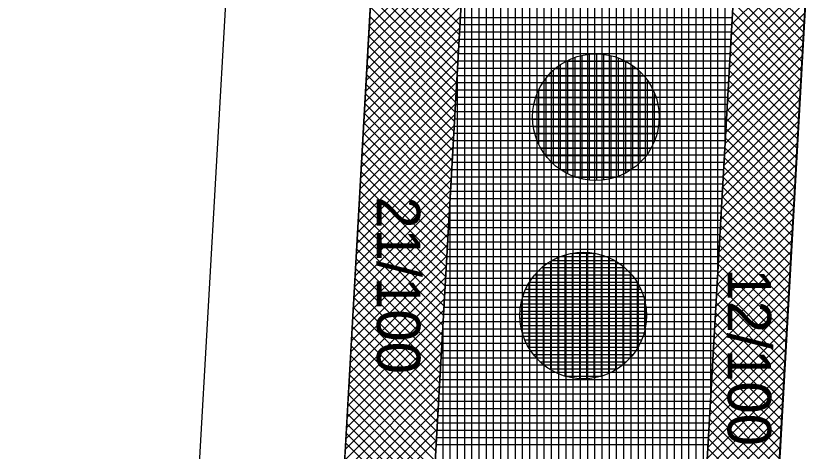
# Model space of a CAD drawing. Extents: x -565346 to -564154, y -1097386 to -1095620.
# Drawn here: x -564304.4 to -564282.47, y -1097114.37 to -1097102.35 of the extents above; entities that cross this region are included whole.
import ezdxf

# ---------------------------------------------------------------- set-up
doc = ezdxf.new("R2010")
doc.units = 0
for name, color, linetype in [('Vrstva 1', 7, 'Continuous'), ('Vrstva 13', 7, 'Continuous'), ('Vrstva 40', 7, 'Continuous'), ('Vrstva 41', 7, 'Continuous'), ('Vrstva 42', 7, 'Continuous'), ('Vrstva 43', 7, 'Continuous'), ('Vrstva 44', 7, 'Continuous')]:
    doc.layers.add(name, color=color, linetype=linetype)

msp = doc.modelspace()

# ---------------------------------------------------------------- linework, layer by layer
at = {"layer": 'Vrstva 1'}
for p, q in [((-564296.5, -1097135.53), (-564285.9, -1096948.97)), ((-564296.48, -1097064.53), (-564302.81, -1097176.11))]:
    msp.add_line(p, q, dxfattribs=at)
at = {"layer": 'Vrstva 13'}
msp.add_line((-564277.71, -1097016.43), (-564284.61, -1097137.94), dxfattribs=at)
at = {"layer": 'Vrstva 41'}
for points in [[(-564296.782, -1097140.492), (-564294.286, -1097140.634), (-564282.373, -1096930.972), (-564284.87, -1096930.83)], [(-564272.899, -1096931.51), (-564274.888, -1096931.397), (-564286.791, -1097141.059), (-564284.798, -1097141.172)]]:
    msp.add_lwpolyline(points, close=True, dxfattribs=at)
at = {"layer": 'Vrstva 42'}
for p, q in [((-564291.976, -1097099.978), (-564294.631, -1097102.633)), ((-564291.993, -1097100.278), (-564294.648, -1097102.933)), ((-564294.494, -1097100.221), (-564292.124, -1097102.591)), ((-564294.509, -1097100.489), (-564292.14, -1097102.858)), ((-564282.487, -1097100.46), (-564284.606, -1097102.579)), ((-564292.01, -1097100.578), (-564294.665, -1097103.233)), ((-564284.496, -1097100.643), (-564282.605, -1097102.534)), ((-564292.027, -1097100.878), (-564294.682, -1097103.533)), ((-564294.524, -1097100.757), (-564292.155, -1097103.126)), ((-564282.504, -1097100.76), (-564284.623, -1097102.879)), ((-564284.512, -1097100.91), (-564282.62, -1097102.802)), ((-564294.539, -1097101.024), (-564292.17, -1097103.394)), ((-564282.521, -1097101.059), (-564284.64, -1097103.179)), ((-564292.044, -1097101.178), (-564294.699, -1097103.833)), ((-564294.555, -1097101.292), (-564292.185, -1097103.661)), ((-564282.538, -1097101.359), (-564284.657, -1097103.478)), ((-564284.527, -1097101.178), (-564282.635, -1097103.069)), ((-564292.061, -1097101.478), (-564294.716, -1097104.132)), ((-564294.57, -1097101.559), (-564292.2, -1097103.929)), ((-564284.542, -1097101.446), (-564282.651, -1097103.337)), ((-564292.078, -1097101.777), (-564294.733, -1097104.432)), ((-564294.585, -1097101.827), (-564292.216, -1097104.196)), ((-564282.555, -1097101.659), (-564284.674, -1097103.778)), ((-564284.557, -1097101.713), (-564282.666, -1097103.605)), ((-564282.572, -1097101.959), (-564284.692, -1097104.078)), ((-564284.572, -1097101.981), (-564282.681, -1097103.872)), ((-564292.095, -1097102.077), (-564294.75, -1097104.732)), ((-564294.6, -1097102.095), (-564292.231, -1097104.464)), ((-564282.589, -1097102.259), (-564284.709, -1097104.378)), ((-564284.588, -1097102.249), (-564282.696, -1097104.14)), ((-564292.112, -1097102.377), (-564294.767, -1097105.032)), ((-564294.615, -1097102.362), (-564292.246, -1097104.732)), ((-564292.129, -1097102.677), (-564294.784, -1097105.332)), ((-564294.631, -1097102.63), (-564292.261, -1097104.999)), ((-564282.606, -1097102.559), (-564284.726, -1097104.678)), ((-564284.603, -1097102.516), (-564282.711, -1097104.408)), ((-564294.646, -1097102.898), (-564292.276, -1097105.267)), ((-564282.623, -1097102.859), (-564284.743, -1097104.978)), ((-564284.618, -1097102.784), (-564282.727, -1097104.675)), ((-564292.146, -1097102.977), (-564294.801, -1097105.632)), ((-564284.633, -1097103.052), (-564282.742, -1097104.943)), ((-564292.163, -1097103.277), (-564294.818, -1097105.932)), ((-564294.661, -1097103.165), (-564292.292, -1097105.535)), ((-564282.64, -1097103.158), (-564284.76, -1097105.278)), ((-564284.648, -1097103.319), (-564282.757, -1097105.211)), ((-564292.18, -1097103.577), (-564294.835, -1097106.232)), ((-564294.676, -1097103.433), (-564292.307, -1097105.802)), ((-564282.657, -1097103.458), (-564284.777, -1097105.577)), ((-564284.664, -1097103.587), (-564282.772, -1097105.478)), ((-564294.691, -1097103.701), (-564292.322, -1097106.07)), ((-564282.675, -1097103.758), (-564284.794, -1097105.877)), ((-564292.197, -1097103.877), (-564294.852, -1097106.531)), ((-564294.707, -1097103.968), (-564292.337, -1097106.338)), ((-564284.679, -1097103.854), (-564282.787, -1097105.746)), ((-564292.214, -1097104.177), (-564294.869, -1097106.831)), ((-564294.722, -1097104.236), (-564292.352, -1097106.605)), ((-564282.692, -1097104.058), (-564284.811, -1097106.177)), ((-564284.694, -1097104.122), (-564282.803, -1097106.014)), ((-564282.709, -1097104.358), (-564284.828, -1097106.477)), ((-564284.709, -1097104.39), (-564282.818, -1097106.281)), ((-564292.232, -1097104.476), (-564294.886, -1097107.131)), ((-564294.737, -1097104.503), (-564292.368, -1097106.873)), ((-564282.726, -1097104.658), (-564284.845, -1097106.777)), ((-564284.724, -1097104.657), (-564282.833, -1097106.549)), ((-564292.249, -1097104.776), (-564294.903, -1097107.431)), ((-564294.752, -1097104.771), (-564292.383, -1097107.14)), ((-564292.266, -1097105.076), (-564294.92, -1097107.731)), ((-564294.767, -1097105.039), (-564292.398, -1097107.408)), ((-564282.743, -1097104.958), (-564284.862, -1097107.077)), ((-564284.74, -1097104.925), (-564282.848, -1097106.817)), ((-564294.783, -1097105.306), (-564292.413, -1097107.676)), ((-564282.76, -1097105.257), (-564284.879, -1097107.377)), ((-564284.755, -1097105.193), (-564282.863, -1097107.084)), ((-564292.283, -1097105.376), (-564294.937, -1097108.031)), ((-564282.777, -1097105.557), (-564284.896, -1097107.677)), ((-564284.77, -1097105.46), (-564282.878, -1097107.352)), ((-564292.3, -1097105.676), (-564294.955, -1097108.331)), ((-564294.798, -1097105.574), (-564292.429, -1097107.943)), ((-564284.785, -1097105.728), (-564282.894, -1097107.62)), ((-564292.317, -1097105.976), (-564294.972, -1097108.631)), ((-564294.813, -1097105.842), (-564292.444, -1097108.211)), ((-564282.794, -1097105.857), (-564284.913, -1097107.976)), ((-564284.8, -1097105.996), (-564282.909, -1097107.887)), ((-564294.828, -1097106.109), (-564292.459, -1097108.479)), ((-564282.811, -1097106.157), (-564284.93, -1097108.276)), ((-564292.334, -1097106.276), (-564294.989, -1097108.931)), ((-564294.844, -1097106.377), (-564292.474, -1097108.746)), ((-564284.816, -1097106.263), (-564282.924, -1097108.155)), ((-564292.351, -1097106.576), (-564295.006, -1097109.23)), ((-564294.859, -1097106.645), (-564292.489, -1097109.014)), ((-564282.828, -1097106.457), (-564284.947, -1097108.576)), ((-564284.831, -1097106.531), (-564282.939, -1097108.422)), ((-564292.368, -1097106.875), (-564295.023, -1097109.53)), ((-564282.845, -1097106.757), (-564284.964, -1097108.876)), ((-564284.846, -1097106.799), (-564282.954, -1097108.69)), ((-564294.874, -1097106.912), (-564292.505, -1097109.282)), ((-564282.862, -1097107.057), (-564284.981, -1097109.176)), ((-564284.861, -1097107.066), (-564282.97, -1097108.958)), ((-564292.385, -1097107.175), (-564295.04, -1097109.83)), ((-564294.889, -1097107.18), (-564292.52, -1097109.549)), ((-564292.402, -1097107.475), (-564295.057, -1097110.13)), ((-564294.904, -1097107.447), (-564292.535, -1097109.817)), ((-564282.879, -1097107.356), (-564284.998, -1097109.476)), ((-564284.876, -1097107.334), (-564282.985, -1097109.225)), ((-564294.92, -1097107.715), (-564292.55, -1097110.084)), ((-564282.896, -1097107.656), (-564285.015, -1097109.776)), ((-564284.892, -1097107.602), (-564283, -1097109.493)), ((-564292.419, -1097107.775), (-564295.074, -1097110.43)), ((-564282.913, -1097107.956), (-564285.032, -1097110.075)), ((-564284.907, -1097107.869), (-564283.015, -1097109.761)), ((-564292.436, -1097108.075), (-564295.091, -1097110.73)), ((-564294.935, -1097107.983), (-564292.565, -1097110.352)), ((-564284.922, -1097108.137), (-564283.03, -1097110.028)), ((-564292.453, -1097108.375), (-564295.108, -1097111.03)), ((-564294.95, -1097108.25), (-564292.581, -1097110.62)), ((-564282.93, -1097108.256), (-564285.049, -1097110.375)), ((-564284.937, -1097108.404), (-564283.046, -1097110.296)), ((-564294.965, -1097108.518), (-564292.596, -1097110.887)), ((-564282.947, -1097108.556), (-564285.066, -1097110.675)), ((-564292.47, -1097108.675), (-564295.125, -1097111.33)), ((-564294.98, -1097108.786), (-564292.611, -1097111.155)), ((-564284.952, -1097108.672), (-564283.061, -1097110.564)), ((-564292.487, -1097108.975), (-564295.142, -1097111.629)), ((-564294.996, -1097109.053), (-564292.626, -1097111.423)), ((-564282.964, -1097108.856), (-564285.083, -1097110.975)), ((-564284.968, -1097108.94), (-564283.076, -1097110.831)), ((-564292.504, -1097109.274), (-564295.159, -1097111.929)), ((-564282.981, -1097109.156), (-564285.1, -1097111.275)), ((-564284.983, -1097109.207), (-564283.091, -1097111.099)), ((-564295.011, -1097109.321), (-564292.641, -1097111.69)), ((-564282.998, -1097109.456), (-564285.117, -1097111.575)), ((-564284.998, -1097109.475), (-564283.106, -1097111.367)), ((-564292.521, -1097109.574), (-564295.176, -1097112.229)), ((-564295.026, -1097109.589), (-564292.657, -1097111.958)), ((-564292.538, -1097109.874), (-564295.193, -1097112.529)), ((-564295.041, -1097109.856), (-564292.672, -1097112.226)), ((-564283.015, -1097109.755), (-564285.134, -1097111.875)), ((-564285.013, -1097109.743), (-564283.121, -1097111.634)), ((-564295.056, -1097110.124), (-564292.687, -1097112.493)), ((-564283.032, -1097110.055), (-564285.151, -1097112.175)), ((-564285.028, -1097110.01), (-564283.137, -1097111.902)), ((-564292.555, -1097110.174), (-564295.21, -1097112.829)), ((-564283.049, -1097110.355), (-564285.168, -1097112.474)), ((-564285.043, -1097110.278), (-564283.152, -1097112.17)), ((-564292.572, -1097110.474), (-564295.227, -1097113.129)), ((-564295.072, -1097110.391), (-564292.702, -1097112.761)), ((-564285.059, -1097110.546), (-564283.167, -1097112.437)), ((-564292.589, -1097110.774), (-564295.244, -1097113.429)), ((-564295.087, -1097110.659), (-564292.717, -1097113.028)), ((-564283.066, -1097110.655), (-564285.185, -1097112.774)), ((-564285.074, -1097110.813), (-564283.182, -1097112.705)), ((-564295.102, -1097110.927), (-564292.733, -1097113.296)), ((-564283.083, -1097110.955), (-564285.202, -1097113.074)), ((-564292.606, -1097111.074), (-564295.261, -1097113.729)), ((-564295.117, -1097111.194), (-564292.748, -1097113.564)), ((-564283.1, -1097111.255), (-564285.219, -1097113.374)), ((-564285.089, -1097111.081), (-564283.197, -1097112.973)), ((-564292.623, -1097111.374), (-564295.278, -1097114.028)), ((-564295.132, -1097111.462), (-564292.763, -1097113.831)), ((-564285.104, -1097111.349), (-564283.213, -1097113.24)), ((-564292.64, -1097111.674), (-564295.295, -1097114.328)), ((-564283.117, -1097111.555), (-564285.236, -1097113.674)), ((-564285.119, -1097111.616), (-564283.228, -1097113.508)), ((-564295.148, -1097111.73), (-564292.778, -1097114.099)), ((-564283.134, -1097111.854), (-564285.253, -1097113.974)), ((-564285.135, -1097111.884), (-564283.243, -1097113.776)), ((-564292.658, -1097111.973), (-564295.312, -1097114.628)), ((-564295.163, -1097111.997), (-564292.793, -1097114.367)), ((-564292.675, -1097112.273), (-564295.329, -1097114.928)), ((-564295.178, -1097112.265), (-564292.809, -1097114.634)), ((-564283.151, -1097112.154), (-564285.27, -1097114.274)), ((-564285.15, -1097112.152), (-564283.258, -1097114.043)), ((-564292.692, -1097112.573), (-564295.346, -1097115.228)), ((-564295.193, -1097112.533), (-564292.824, -1097114.902)), ((-564283.168, -1097112.454), (-564285.287, -1097114.573)), ((-564285.165, -1097112.419), (-564283.273, -1097114.311)), ((-564283.185, -1097112.754), (-564285.304, -1097114.873)), ((-564285.18, -1097112.687), (-564283.289, -1097114.579)), ((-564292.709, -1097112.873), (-564295.363, -1097115.528)), ((-564295.208, -1097112.8), (-564292.839, -1097115.17)), ((-564285.195, -1097112.955), (-564283.304, -1097114.846)), ((-564292.726, -1097113.173), (-564295.38, -1097115.828)), ((-564295.224, -1097113.068), (-564292.854, -1097115.437)), ((-564283.202, -1097113.054), (-564285.321, -1097115.173)), ((-564285.211, -1097113.222), (-564283.319, -1097115.114)), ((-564295.239, -1097113.335), (-564292.87, -1097115.705)), ((-564283.219, -1097113.354), (-564285.338, -1097115.473)), ((-564292.743, -1097113.473), (-564295.397, -1097116.128)), ((-564295.254, -1097113.603), (-564292.885, -1097115.972)), ((-564283.236, -1097113.654), (-564285.355, -1097115.773)), ((-564285.226, -1097113.49), (-564283.334, -1097115.381)), ((-564292.76, -1097113.773), (-564295.415, -1097116.427)), ((-564295.269, -1097113.871), (-564292.9, -1097116.24)), ((-564285.241, -1097113.757), (-564283.349, -1097115.649)), ((-564292.777, -1097114.073), (-564295.432, -1097116.727)), ((-564283.253, -1097113.953), (-564285.372, -1097116.073)), ((-564285.256, -1097114.025), (-564283.365, -1097115.917)), ((-564295.284, -1097114.138), (-564292.915, -1097116.508)), ((-564283.27, -1097114.253), (-564285.389, -1097116.373)), ((-564285.271, -1097114.293), (-564283.38, -1097116.184))]:
    msp.add_line(p, q, dxfattribs=at)
at = {"layer": 'Vrstva 43'}
for p, q in [((-564284.79, -1097105.813), (-564284.79, -1096973.51)), ((-564284.99, -1097109.336), (-564284.99, -1096977.03)), ((-564285.19, -1097112.859), (-564285.19, -1096980.55)), ((-564285.39, -1097116.382), (-564285.39, -1096984.069)), ((-564285.59, -1097119.904), (-564285.59, -1096987.589)), ((-564285.79, -1097123.427), (-564285.79, -1096991.109)), ((-564285.99, -1097126.95), (-564285.99, -1096994.629)), ((-564286.19, -1097130.473), (-564286.19, -1096998.149)), ((-564286.39, -1097133.996), (-564286.39, -1097001.669)), ((-564286.59, -1097137.519), (-564286.59, -1097005.189)), ((-564286.79, -1097141.041), (-564286.79, -1097008.709)), ((-564286.99, -1097151.064), (-564286.99, -1097012.229)), ((-564287.19, -1097151.053), (-564287.19, -1097015.748)), ((-564287.39, -1097151.606), (-564287.39, -1097019.268)), ((-564287.59, -1097155.126), (-564287.59, -1097022.788)), ((-564287.79, -1097158.646), (-564287.79, -1097026.308)), ((-564287.99, -1097162.166), (-564287.99, -1097029.828)), ((-564288.19, -1097165.686), (-564288.19, -1097033.348)), ((-564288.39, -1097169.206), (-564288.39, -1097036.868)), ((-564288.59, -1097172.726), (-564288.59, -1097040.388)), ((-564288.79, -1097176.246), (-564288.79, -1097043.908)), ((-564288.99, -1097179.766), (-564288.99, -1097047.427)), ((-564289.19, -1097183.288), (-564289.19, -1097050.947)), ((-564289.39, -1097186.812), (-564289.39, -1097054.467)), ((-564289.59, -1097190.335), (-564289.59, -1097057.987)), ((-564289.79, -1097193.858), (-564289.79, -1097061.507)), ((-564289.99, -1097197.382), (-564289.99, -1097065.027)), ((-564290.19, -1097200.905), (-564290.19, -1097068.547)), ((-564290.39, -1097204.428), (-564290.39, -1097072.067)), ((-564290.59, -1097207.951), (-564290.59, -1097075.587)), ((-564290.79, -1097211.475), (-564290.79, -1097079.106)), ((-564290.99, -1097214.998), (-564290.99, -1097082.626)), ((-564291.19, -1097218.521), (-564291.19, -1097086.146)), ((-564291.39, -1097222.044), (-564291.39, -1097089.666)), ((-564291.59, -1097225.568), (-564291.59, -1097093.186)), ((-564291.79, -1097229.091), (-564291.79, -1097096.706)), ((-564291.99, -1097232.614), (-564291.99, -1097100.226)), ((-564292.113, -1097102.39), (-564284.596, -1097102.39)), ((-564292.124, -1097102.59), (-564284.607, -1097102.59)), ((-564292.136, -1097102.79), (-564284.618, -1097102.79)), ((-564292.147, -1097102.99), (-564284.63, -1097102.99)), ((-564292.158, -1097103.19), (-564284.641, -1097103.19)), ((-564292.17, -1097103.39), (-564284.652, -1097103.39)), ((-564292.193, -1097103.79), (-564284.675, -1097103.79)), ((-564292.19, -1097236.137), (-564292.19, -1097103.746)), ((-564292.181, -1097103.59), (-564284.664, -1097103.59)), ((-564292.204, -1097103.99), (-564284.687, -1097103.99)), ((-564292.215, -1097104.19), (-564284.698, -1097104.19)), ((-564292.227, -1097104.39), (-564284.709, -1097104.39)), ((-564292.238, -1097104.59), (-564284.721, -1097104.59)), ((-564292.249, -1097104.79), (-564284.732, -1097104.79)), ((-564292.261, -1097104.99), (-564284.743, -1097104.99)), ((-564292.272, -1097105.19), (-564284.755, -1097105.19)), ((-564292.283, -1097105.39), (-564284.766, -1097105.39)), ((-564292.295, -1097105.59), (-564284.777, -1097105.59)), ((-564292.318, -1097105.99), (-564284.8, -1097105.99)), ((-564292.306, -1097105.79), (-564284.789, -1097105.79)), ((-564292.329, -1097106.19), (-564284.811, -1097106.19)), ((-564292.34, -1097106.39), (-564284.823, -1097106.39)), ((-564292.352, -1097106.59), (-564284.834, -1097106.59)), ((-564292.363, -1097106.79), (-564284.845, -1097106.79)), ((-564292.374, -1097106.99), (-564284.857, -1097106.99)), ((-564292.39, -1097239.661), (-564292.39, -1097107.266)), ((-564292.386, -1097107.19), (-564284.868, -1097107.19)), ((-564292.397, -1097107.39), (-564284.88, -1097107.39)), ((-564292.408, -1097107.59), (-564284.891, -1097107.59)), ((-564292.42, -1097107.79), (-564284.902, -1097107.79)), ((-564292.443, -1097108.19), (-564284.925, -1097108.19)), ((-564292.431, -1097107.99), (-564284.914, -1097107.99)), ((-564292.454, -1097108.39), (-564284.936, -1097108.39)), ((-564292.465, -1097108.59), (-564284.948, -1097108.59)), ((-564292.477, -1097108.79), (-564284.959, -1097108.79)), ((-564292.488, -1097108.99), (-564284.97, -1097108.99)), ((-564292.499, -1097109.19), (-564284.982, -1097109.19)), ((-564292.511, -1097109.39), (-564284.993, -1097109.39)), ((-564292.522, -1097109.59), (-564285.004, -1097109.59)), ((-564292.533, -1097109.79), (-564285.016, -1097109.79)), ((-564292.545, -1097109.99), (-564285.027, -1097109.99)), ((-564292.556, -1097110.19), (-564285.038, -1097110.19)), ((-564292.579, -1097110.59), (-564285.061, -1097110.59)), ((-564292.568, -1097110.39), (-564285.05, -1097110.39)), ((-564292.59, -1097243.184), (-564292.59, -1097110.785)), ((-564292.59, -1097110.79), (-564285.073, -1097110.79)), ((-564292.602, -1097110.99), (-564285.084, -1097110.99)), ((-564292.613, -1097111.19), (-564285.095, -1097111.19)), ((-564292.624, -1097111.39), (-564285.107, -1097111.39)), ((-564292.636, -1097111.59), (-564285.118, -1097111.59)), ((-564292.647, -1097111.79), (-564285.129, -1097111.79)), ((-564292.658, -1097111.99), (-564285.141, -1097111.99)), ((-564292.67, -1097112.19), (-564285.152, -1097112.19)), ((-564292.681, -1097112.39), (-564285.163, -1097112.39)), ((-564292.704, -1097112.79), (-564285.186, -1097112.79)), ((-564292.693, -1097112.59), (-564285.175, -1097112.59)), ((-564292.715, -1097112.99), (-564285.197, -1097112.99)), ((-564292.727, -1097113.19), (-564285.209, -1097113.19)), ((-564292.738, -1097113.39), (-564285.22, -1097113.39)), ((-564292.749, -1097113.59), (-564285.232, -1097113.59)), ((-564292.761, -1097113.79), (-564285.243, -1097113.79)), ((-564292.772, -1097113.99), (-564285.254, -1097113.99)), ((-564292.79, -1097246.707), (-564292.79, -1097114.305)), ((-564292.783, -1097114.19), (-564285.266, -1097114.19))]:
    msp.add_line(p, q, dxfattribs=at)
msp.add_lwpolyline([(-564283.37, -1096906.18), (-564284.87, -1096930.83), (-564282.373, -1096930.972), (-564294.286, -1097140.634), (-564296.782, -1097140.492), (-564297.42, -1097150.37), (-564294.347, -1097150.646), (-564303.226, -1097307.04), (-564304.096, -1097322.37), (-564304.399, -1097332.838), (-564302.848, -1097333.175), (-564297.082, -1097322.329), (-564293.197, -1097253.877), (-564289.027, -1097180.417), (-564287.358, -1097151.043), (-564285.364, -1097151.156), (-564284.798, -1097141.172), (-564286.791, -1097141.059), (-564274.888, -1096931.397), (-564272.899, -1096931.51), (-564271.475, -1096906.55)], dxfattribs=at)
at = {"layer": 'Vrstva 44'}
for p, q in [((-564289.14, -1097106.711), (-564289.14, -1097103.576)), ((-564288.94, -1097106.794), (-564288.94, -1097103.493)), ((-564288.74, -1097106.853), (-564288.74, -1097103.437)), ((-564288.54, -1097106.884), (-564288.54, -1097103.404)), ((-564288.508, -1097103.4), (-564288.246, -1097103.4)), ((-564288.34, -1097106.892), (-564288.34, -1097103.394)), ((-564288.14, -1097106.878), (-564288.14, -1097103.41)), ((-564287.94, -1097106.841), (-564287.94, -1097103.448)), ((-564287.74, -1097106.778), (-564287.74, -1097103.511)), ((-564289.482, -1097103.8), (-564287.245, -1097103.8)), ((-564289.34, -1097106.595), (-564289.34, -1097103.693)), ((-564289.185, -1097103.6), (-564287.541, -1097103.6)), ((-564287.54, -1097106.686), (-564287.54, -1097103.6)), ((-564287.34, -1097106.562), (-564287.34, -1097103.727)), ((-564289.687, -1097104), (-564287.041, -1097104)), ((-564289.54, -1097106.438), (-564289.54, -1097103.849)), ((-564287.14, -1097106.392), (-564287.14, -1097103.894)), ((-564289.835, -1097104.2), (-564286.893, -1097104.2)), ((-564289.74, -1097106.222), (-564289.74, -1097104.066)), ((-564286.94, -1097106.158), (-564286.94, -1097104.129)), ((-564289.948, -1097104.4), (-564286.782, -1097104.4)), ((-564289.94, -1097105.902), (-564289.94, -1097104.385)), ((-564290.026, -1097104.6), (-564286.701, -1097104.6)), ((-564286.74, -1097105.792), (-564286.74, -1097104.497)), ((-564290.078, -1097104.8), (-564286.65, -1097104.8)), ((-564290.107, -1097105), (-564286.622, -1097105)), ((-564290.113, -1097105.2), (-564286.617, -1097105.2)), ((-564290.095, -1097105.4), (-564286.634, -1097105.4)), ((-564290.052, -1097105.6), (-564286.675, -1097105.6)), ((-564289.985, -1097105.8), (-564286.744, -1097105.8)), ((-564289.89, -1097106), (-564286.84, -1097106)), ((-564289.757, -1097106.2), (-564286.969, -1097106.2)), ((-564289.582, -1097106.4), (-564287.148, -1097106.4)), ((-564289.333, -1097106.6), (-564287.397, -1097106.6)), ((-564288.924, -1097106.8), (-564287.803, -1097106.8)), ((-564289.41, -1097112.228), (-564289.41, -1097109.02)), ((-564289.21, -1097112.302), (-564289.21, -1097108.947)), ((-564289.012, -1097108.9), (-564288.425, -1097108.9)), ((-564289.01, -1097112.347), (-564289.01, -1097108.9)), ((-564288.81, -1097112.37), (-564288.81, -1097108.878)), ((-564288.61, -1097112.37), (-564288.61, -1097108.879)), ((-564288.41, -1097112.346), (-564288.41, -1097108.902)), ((-564288.21, -1097112.298), (-564288.21, -1097108.949)), ((-564288.01, -1097112.224), (-564288.01, -1097109.023)), ((-564289.81, -1097111.988), (-564289.81, -1097109.261)), ((-564289.61, -1097112.125), (-564289.61, -1097109.122)), ((-564289.57, -1097109.1), (-564287.857, -1097109.1)), ((-564287.81, -1097112.122), (-564287.81, -1097109.128)), ((-564287.61, -1097111.979), (-564287.61, -1097109.266)), ((-564290.053, -1097109.5), (-564287.373, -1097109.5)), ((-564290.01, -1097111.798), (-564290.01, -1097109.449)), ((-564289.856, -1097109.3), (-564287.572, -1097109.3)), ((-564287.41, -1097111.79), (-564287.41, -1097109.46)), ((-564290.21, -1097111.529), (-564290.21, -1097109.717)), ((-564290.199, -1097109.7), (-564287.23, -1097109.7)), ((-564290.307, -1097109.9), (-564287.122, -1097109.9)), ((-564287.21, -1097111.517), (-564287.21, -1097109.733)), ((-564290.382, -1097110.1), (-564287.045, -1097110.1)), ((-564290.432, -1097110.3), (-564286.996, -1097110.3)), ((-564290.41, -1097111.052), (-564290.41, -1097110.193)), ((-564287.01, -1097111.014), (-564287.01, -1097110.229)), ((-564290.459, -1097110.5), (-564286.971, -1097110.5)), ((-564290.462, -1097110.7), (-564286.967, -1097110.7)), ((-564290.441, -1097110.9), (-564286.987, -1097110.9)), ((-564290.396, -1097111.1), (-564287.031, -1097111.1)), ((-564290.327, -1097111.3), (-564287.102, -1097111.3)), ((-564290.229, -1097111.5), (-564287.201, -1097111.5)), ((-564290.092, -1097111.7), (-564287.336, -1097111.7)), ((-564289.911, -1097111.9), (-564287.518, -1097111.9)), ((-564289.653, -1097112.1), (-564287.776, -1097112.1)), ((-564289.217, -1097112.3), (-564288.217, -1097112.3))]:
    msp.add_line(p, q, dxfattribs=at)
for centre in [(-564288.364, -1097105.144), (-564288.714, -1097110.624)]:
    msp.add_circle(centre, 1.75, dxfattribs=at)

# ---------------------------------------------------------------- texts
at = {"layer": 'Vrstva 40'}
for s, p in [('21/100', (-564294.42, -1097107.33)), ('12/100', (-564284.72, -1097109.32))]:
    msp.add_text(s, height=1.2, rotation=270, dxfattribs=at).set_placement(p)

doc.saveas('drawing.dxf')
